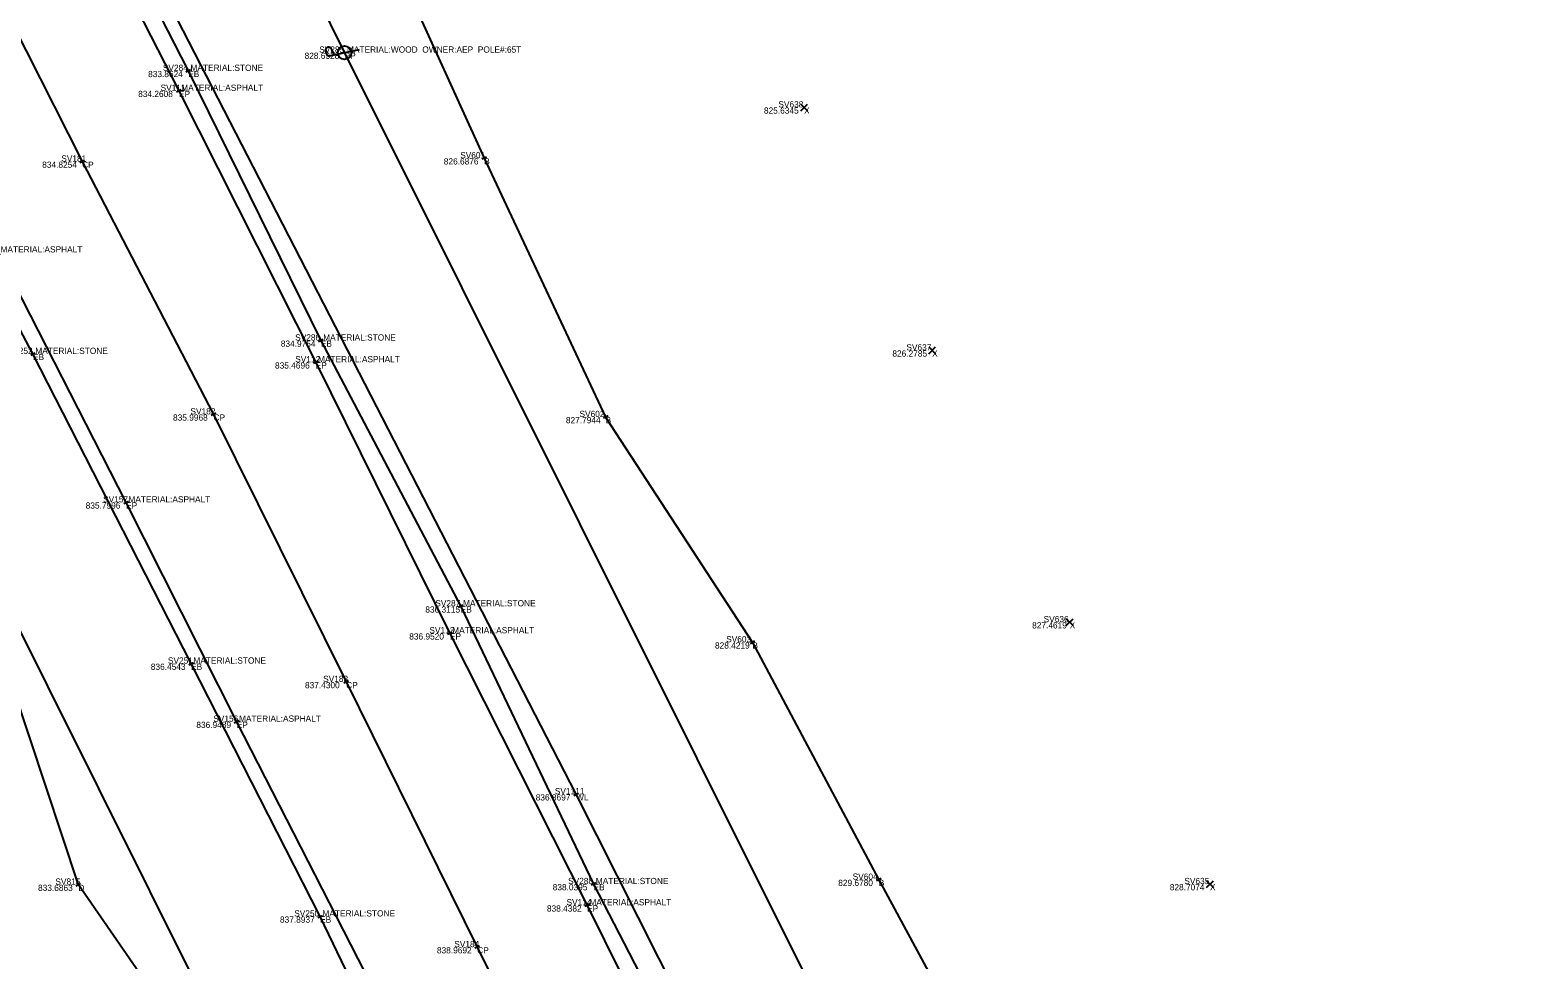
# Model space of a CAD drawing. Extents: x 1715717 to 1717046, y 393954 to 396000.
# Drawn here: x 1716325 to 1716470.3, y 394448.1 to 394537.7 of the extents above; entities that cross this region are included whole.
import ezdxf

# ---------------------------------------------------------------- set-up
doc = ezdxf.new("R2010")
doc.units = 0
for name, color, linetype in [('DR_X_Ditch', 7, 'Continuous'), ('PV_X_COP', 7, 'Continuous'), ('PV_X_EOP', 7, 'Continuous'), ('PV_X_Shoulder', 7, 'Continuous'), ('SV_X_Break_Lines', 7, 'Continuous'), ('SV_X_Random_Point', 7, 'Continuous'), ('SV_X_Shot_Marker', 7, 'Continuous'), ('SV_X_Text_Comment', 7, 'Continuous'), ('SV_X_Text_Description', 7, 'Continuous'), ('SV_X_Text_Elevation', 7, 'Continuous'), ('SV_X_Text_Name', 7, 'Continuous'), ('UT_X_Electric_Cells', 7, 'Continuous'), ('UT_X_Overhead_Electric', 7, 'Continuous'), ('UT_X_Overhead_Telecom', 7, 'Continuous'), ('UT_X_Water', 7, 'Continuous')]:
    doc.layers.add(name, color=color, linetype=linetype)

msp = doc.modelspace()

# ---------------------------------------------------------------- linework, layer by layer
at = {"layer": 'DR_X_Ditch'}
msp.add_lwpolyline([(1716415.68, 394311.25), (1716402.29, 394333.97), (1716389.99, 394357.96), (1716379.12, 394373.82), (1716366.15, 394395.16), (1716353.46, 394415.72), (1716341.62, 394438), (1716329.62, 394455.37), (1716321.72, 394479.13), (1716315.74, 394495.26), (1716304.63, 394514.9), (1716291.1, 394535.86), (1716283.78, 394548.72), (1716269.08, 394579.45), (1716252.09, 394607.64), (1716231.43, 394633.87), (1716225.84, 394642.47), (1716225.38, 394644.39), (1716223.06, 394654.97)], dxfattribs=at)
at = {"layer": 'PV_X_COP'}
msp.add_lwpolyline([(1716316.41, 394551.83), (1716329.98, 394525.07), (1716342.64, 394500.7), (1716355.43, 394474.91), (1716368.06, 394449.35), (1716381.47, 394422.5), (1716394.06, 394396.97), (1716407.48, 394370.48), (1716421.67, 394341.9), (1716435.06, 394315.11), (1716447.6, 394290.07), (1716460.11, 394264.71), (1716472.69, 394239.15), (1716486.08, 394212.5), (1716500.21, 394184.03), (1716512.53, 394158.68), (1716522.87, 394138.69), (1716535.3, 394112.62), (1716550.33, 394081.5)], dxfattribs=at)
at = {"layer": 'PV_X_EOP'}
for p, q in [((1716334.22, 394492.22), (1716321.89, 394516.31)), ((1716344.88, 394471.08), (1716334.22, 394492.22)), ((1716357.27, 394446.91), (1716344.88, 394471.08))]:
    msp.add_line(p, q, dxfattribs=at)
msp.add_lwpolyline([(1716325.75, 394558.4), (1716339.31, 394531.89), (1716352.49, 394505.72), (1716365.43, 394479.6), (1716378.65, 394453.38), (1716392.13, 394426.2), (1716405.28, 394399.09), (1716418.42, 394372.49), (1716430.72, 394347.4), (1716443.91, 394321), (1716457.06, 394294.96), (1716470.53, 394268.03), (1716482.82, 394243.95), (1716495.6, 394217.9), (1716508.99, 394191), (1716522.38, 394163.92), (1716535.04, 394138.11), (1716548.85, 394110.2), (1716560.84, 394086.42)], dxfattribs=at)
at = {"layer": 'PV_X_Shoulder'}
for points in [[(1716418.47, 394320.44), (1716405.03, 394348.07), (1716391.13, 394375.29), (1716377.55, 394402.13), (1716364.92, 394427.41), (1716352.92, 394452.31), (1716340.48, 394476.68), (1716325.24, 394506.53), (1716313.52, 394528.68), (1716299.45, 394557.27), (1716287.17, 394581.09), (1716274.89, 394606.65), (1716262.62, 394630.71), (1716250.75, 394654.85), (1716237.77, 394680.01), (1716227.15, 394700.98), (1716215.23, 394724.01), (1716202.66, 394749.78), (1716192.03, 394770.13)], [(1716326.15, 394561.27), (1716340.2, 394533.81), (1716352.99, 394507.82), (1716366.47, 394482.2), (1716379.27, 394455.43), (1716392.58, 394429.7), (1716405.35, 394404.37), (1716417.24, 394378.92), (1716430.47, 394351.93), (1716443.77, 394325.47), (1716457.4, 394297.65), (1716469.76, 394273.45), (1716482.56, 394247.11), (1716495.52, 394222.32), (1716505.29, 394201.35), (1716519.46, 394171.85)]]:
    msp.add_lwpolyline(points, dxfattribs=at)
at = {"layer": 'SV_X_Break_Lines'}
msp.add_lwpolyline([(1716306.03, 394670.89), (1716310.08, 394661.05), (1716315.83, 394642.61), (1716324.03, 394616.27), (1716336.58, 394593.44), (1716347.74, 394570.77), (1716358.33, 394548.31), (1716368.73, 394525.39), (1716380.44, 394500.45), (1716394.59, 394478.73), (1716406.77, 394455.85), (1716419.35, 394432.59), (1716433.51, 394405.53), (1716449.92, 394385.23), (1716467.09, 394366.28), (1716488, 394358.9)], dxfattribs=at)
at = {"layer": 'SV_X_Random_Point'}
for p, q in [((1716399.24, 394529.96), (1716399.9, 394530.62)), ((1716399.24, 394530.62), (1716399.9, 394529.96)), ((1716411.58, 394506.53), (1716412.24, 394507.2)), ((1716411.58, 394507.2), (1716412.24, 394506.53)), ((1716424.84, 394480.34), (1716425.5, 394481)), ((1716424.84, 394481), (1716425.5, 394480.34)), ((1716438.36, 394455.09), (1716439.03, 394455.76)), ((1716438.36, 394455.76), (1716439.03, 394455.09))]:
    msp.add_line(p, q, dxfattribs=at)
at = {"layer": 'SV_X_Shot_Marker'}
for p, q in [((1716340.42, 394533.92), (1716339.98, 394533.69)), ((1716340.09, 394534.03), (1716340.32, 394533.58)), ((1716340.2, 394533.81), (1716340.2, 394533.81)), ((1716339.53, 394532), (1716339.08, 394531.77)), ((1716339.19, 394532.11), (1716339.42, 394531.66)), ((1716339.31, 394531.89), (1716339.31, 394531.89)), ((1716330.2, 394525.18), (1716329.75, 394524.95)), ((1716329.86, 394525.29), (1716330.09, 394524.84)), ((1716329.98, 394525.07), (1716329.98, 394525.07)), ((1716368.95, 394525.5), (1716368.5, 394525.29)), ((1716368.62, 394525.62), (1716368.83, 394525.17)), ((1716368.73, 394525.39), (1716368.73, 394525.39)), ((1716353.22, 394507.93), (1716352.77, 394507.71)), ((1716352.88, 394508.04), (1716353.1, 394507.59)), ((1716352.99, 394507.82), (1716352.99, 394507.82)), ((1716325.02, 394506.42), (1716325.46, 394506.65)), ((1716325.36, 394506.31), (1716325.13, 394506.76)), ((1716325.24, 394506.53), (1716325.24, 394506.53)), ((1716352.72, 394505.83), (1716352.27, 394505.6)), ((1716352.38, 394505.94), (1716352.61, 394505.49)), ((1716352.49, 394505.72), (1716352.49, 394505.72)), ((1716342.86, 394500.82), (1716342.41, 394500.59)), ((1716342.52, 394500.93), (1716342.75, 394500.48)), ((1716342.64, 394500.7), (1716342.64, 394500.7)), ((1716380.67, 394500.56), (1716380.22, 394500.35)), ((1716380.34, 394500.68), (1716380.55, 394500.23)), ((1716380.44, 394500.45), (1716380.44, 394500.45)), ((1716334.34, 394491.99), (1716334.11, 394492.44)), ((1716334, 394492.1), (1716334.45, 394492.33)), ((1716334.22, 394492.22), (1716334.22, 394492.22)), ((1716366.69, 394482.31), (1716366.24, 394482.08)), ((1716366.35, 394482.42), (1716366.58, 394481.98)), ((1716366.47, 394482.2), (1716366.47, 394482.2)), ((1716365.66, 394479.71), (1716365.21, 394479.49)), ((1716365.32, 394479.82), (1716365.55, 394479.37)), ((1716365.43, 394479.6), (1716365.43, 394479.6)), ((1716394.8, 394478.86), (1716394.38, 394478.59)), ((1716394.45, 394478.94), (1716394.72, 394478.52)), ((1716394.59, 394478.73), (1716394.59, 394478.73)), ((1716340.26, 394476.56), (1716340.7, 394476.79)), ((1716340.59, 394476.45), (1716340.37, 394476.9)), ((1716340.48, 394476.68), (1716340.48, 394476.68)), ((1716355.66, 394475.02), (1716355.21, 394474.8)), ((1716355.32, 394475.13), (1716355.54, 394474.69)), ((1716355.43, 394474.91), (1716355.43, 394474.91)), ((1716344.65, 394470.97), (1716345.1, 394471.2)), ((1716344.99, 394470.86), (1716344.76, 394471.31)), ((1716344.88, 394471.08), (1716344.88, 394471.08)), ((1716377.37, 394463.98), (1716377.81, 394464.2)), ((1716377.7, 394463.87), (1716377.48, 394464.31)), ((1716377.59, 394464.09), (1716377.59, 394464.09)), ((1716406.65, 394456.07), (1716406.88, 394455.63)), ((1716329.42, 394455.23), (1716329.83, 394455.51)), ((1716329.76, 394455.17), (1716329.48, 394455.58)), ((1716329.62, 394455.37), (1716329.62, 394455.37)), ((1716379.5, 394455.54), (1716379.05, 394455.32)), ((1716379.17, 394455.66), (1716379.38, 394455.21)), ((1716379.27, 394455.43), (1716379.27, 394455.43)), ((1716406.99, 394455.96), (1716406.55, 394455.73)), ((1716406.77, 394455.85), (1716406.77, 394455.85)), ((1716378.87, 394453.49), (1716378.43, 394453.26)), ((1716378.54, 394453.6), (1716378.76, 394453.15)), ((1716378.65, 394453.38), (1716378.65, 394453.38)), ((1716352.7, 394452.2), (1716353.15, 394452.41)), ((1716353.03, 394452.08), (1716352.81, 394452.53)), ((1716352.92, 394452.31), (1716352.92, 394452.31)), ((1716368.29, 394449.46), (1716367.84, 394449.24)), ((1716367.95, 394449.57), (1716368.17, 394449.13)), ((1716368.06, 394449.35), (1716368.06, 394449.35))]:
    msp.add_line(p, q, dxfattribs=at)
at = {"layer": 'UT_X_Electric_Cells'}
for p, q in [((1716353.65, 394535.24), (1716353.46, 394535.62)), ((1716353.65, 394535.24), (1716356.7, 394535.87)), ((1716354.3, 394535.37), (1716354.03, 394535.91))]:
    msp.add_line(p, q, dxfattribs=at)
msp.add_circle((1716355.28, 394535.57), 0.65, dxfattribs=at)
msp.add_arc((1716353.75, 394535.77), 0.319, 25.4624, 207.709, dxfattribs=at)
at = {"layer": 'UT_X_Overhead_Electric'}
for p, q in [((1716355.28, 394535.61), (1716230.45, 394787.5)), ((1716495.47, 394254.94), (1716355.28, 394535.61))]:
    msp.add_line(p, q, dxfattribs=at)
at = {"layer": 'UT_X_Overhead_Telecom'}
msp.add_line((1716302.69, 394522.5), (1716377.83, 394371.81), dxfattribs=at)
at = {"layer": 'UT_X_Water'}
msp.add_line((1716377.59, 394464.09), (1716336.35, 394544.25), dxfattribs=at)
msp.add_lwpolyline([(1716467.94, 394283.7), (1716435.43, 394349.37), (1716377.59, 394464.09)], dxfattribs=at)

# ---------------------------------------------------------------- texts
at = {"layer": 'SV_X_Text_Comment'}
for s, p in [('PP', (1716355.28, 394534.97)), ('EB', (1716340.2, 394533.21)), ('EP', (1716339.31, 394531.29)), ('X', (1716399.57, 394529.69)), ('CP', (1716329.98, 394524.47)), ('B', (1716368.73, 394524.79)), ('EB', (1716352.99, 394507.22)), ('EB', (1716325.24, 394505.93)), ('EP', (1716352.49, 394505.12)), ('X', (1716411.91, 394506.27)), ('CP', (1716342.64, 394500.1)), ('B', (1716380.44, 394499.85)), ('EP', (1716334.22, 394491.62)), ('EB', (1716366.47, 394481.6)), ('EP', (1716365.43, 394479)), ('X', (1716425.17, 394480.07)), ('B', (1716394.59, 394478.13)), ('EB', (1716340.48, 394476.08)), ('CP', (1716355.43, 394474.31)), ('EP', (1716344.88, 394470.48)), ('WL', (1716377.59, 394463.49)), ('D', (1716329.62, 394454.77)), ('EB', (1716379.27, 394454.83)), ('B', (1716406.77, 394455.25)), ('X', (1716438.69, 394454.83)), ('EP', (1716378.65, 394452.78)), ('EB', (1716352.92, 394451.71)), ('CP', (1716368.06, 394448.75))]:
    msp.add_text(s, height=0.6, dxfattribs=at).set_placement(p)
at = {"layer": 'SV_X_Text_Description'}
for s, p in [(' MATERIAL:WOOD  OWNER:AEP  POLE#:65T ', (1716355.28, 394535.57)), (' MATERIAL:STONE ', (1716340.2, 394533.81)), (' MATERIAL:ASPHALT ', (1716339.31, 394531.89)), (' MATERIAL:ASPHALT ', (1716321.89, 394516.31)), (' MATERIAL:STONE ', (1716352.99, 394507.82)), (' MATERIAL:STONE ', (1716325.24, 394506.53)), (' MATERIAL:ASPHALT ', (1716352.49, 394505.72)), (' MATERIAL:ASPHALT ', (1716334.22, 394492.22)), (' MATERIAL:STONE ', (1716366.47, 394482.2)), (' MATERIAL:ASPHALT ', (1716365.43, 394479.6)), (' MATERIAL:STONE ', (1716340.48, 394476.68)), (' MATERIAL:ASPHALT ', (1716344.88, 394471.08)), (' MATERIAL:STONE ', (1716379.27, 394455.43)), (' MATERIAL:ASPHALT ', (1716378.65, 394453.38)), (' MATERIAL:STONE ', (1716352.92, 394452.31))]:
    msp.add_text(s, height=0.6, dxfattribs=at).set_placement(p)
at = {"layer": 'SV_X_Text_Elevation'}
for s, p in [('828.6328', (1716351.42, 394534.97)), ('833.8624', (1716336.34, 394533.21)), ('834.2608', (1716335.38, 394531.29)), ('825.6345', (1716395.7, 394529.69)), ('834.8254', (1716326.13, 394524.47)), ('826.6876', (1716364.84, 394524.79)), ('834.9754', (1716349.13, 394507.22)), ('835.4696', (1716348.57, 394505.12)), ('826.2785', (1716408.08, 394506.27)), ('835.9968', (1716338.74, 394500.1)), ('827.7944', (1716376.61, 394499.85)), ('835.7996', (1716330.32, 394491.62)), ('836.3115', (1716363.06, 394481.6)), ('836.9520', (1716361.51, 394479)), ('827.4619', (1716421.55, 394480.07)), ('828.4219', (1716390.98, 394478.13)), ('836.4543', (1716336.6, 394476.08)), ('837.4300', (1716351.46, 394474.31)), ('836.9489', (1716340.99, 394470.48)), ('836.8697', (1716373.7, 394463.49)), ('833.6863', (1716325.73, 394454.77)), ('838.0395', (1716375.34, 394454.83)), ('829.6780', (1716402.86, 394455.25)), ('828.7074', (1716434.82, 394454.83)), ('838.4382', (1716374.78, 394452.78)), ('837.8937', (1716349.05, 394451.71)), ('838.9692', (1716364.18, 394448.75))]:
    msp.add_text(s, height=0.6, dxfattribs=at).set_placement(p)
at = {"layer": 'SV_X_Text_Name'}
for s, p in [('SV285', (1716352.83, 394535.57)), ('SV284', (1716337.76, 394533.81)), ('SV111', (1716337.54, 394531.89)), ('SV638', (1716397.09, 394530.29)), ('SV601', (1716366.42, 394525.39)), ('SV181', (1716327.97, 394525.07)), ('SV286', (1716350.51, 394507.82)), ('SV252', (1716322.8, 394506.53)), ('SV637', (1716409.43, 394506.87)), ('SV112', (1716350.52, 394505.72)), ('SV182', (1716340.42, 394500.7)), ('SV602', (1716377.92, 394500.45)), ('SV157', (1716332, 394492.22)), ('SV287', (1716364.02, 394482.2)), ('SV636', (1716422.66, 394480.67)), ('SV113', (1716363.45, 394479.6)), ('SV603', (1716392.06, 394478.73)), ('SV251', (1716338.25, 394476.68)), ('SV183', (1716353.21, 394474.91)), ('SV156', (1716342.62, 394471.08)), ('SV1111', (1716375.54, 394464.09)), ('SV288', (1716376.82, 394455.43)), ('SV604', (1716404.25, 394455.85)), ('SV635', (1716436.22, 394455.43)), ('SV815', (1716327.4, 394455.37)), ('SV114', (1716376.67, 394453.38)), ('SV250', (1716350.42, 394452.31)), ('SV184', (1716365.85, 394449.35))]:
    msp.add_text(s, height=0.6, dxfattribs=at).set_placement(p)

doc.saveas('drawing.dxf')
